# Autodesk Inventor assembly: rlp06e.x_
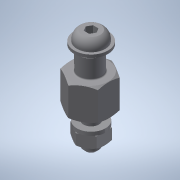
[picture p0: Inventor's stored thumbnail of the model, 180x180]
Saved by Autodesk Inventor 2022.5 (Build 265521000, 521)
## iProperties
Part Number: rlp06e.x_
Material: 一般
Document SubType Name: Assembly
Designer: ImaoCorp
Sending System: SOLIDWORKS 2017-2017317
MC: AMD64
MC_MODEL: Intel64 Family 6 Model 60 Stepping 3, GenuineIntel
OS: Windows_NT
FRU: Parasolid Version 29.0, build 201,  4-17-2017
FORMAT: text
GUISE: transmit
KEY: rlp06e
FILE: rlp06e.x_t
DATE: Wed Sep 04 15:58:59 2019
Author: ImaoCorp
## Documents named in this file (3)
- X:\14_SW2022-Inv2022\00_全2023-1023新製品(TCC)まで\r\rlp06e\RLP06E.iam
- X:\14_SW2022-Inv2022\00_全2023-1023新製品(TCC)まで\r\rlp06e\rlp06e_01.ipt
- X:\14_SW2022-Inv2022\00_全2023-1023新製品(TCC)まで\r\rlp06e\rlp06e_02.ipt
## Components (2 placed, 2 different names)
1. rlp06e_01
2. rlp06e_02
